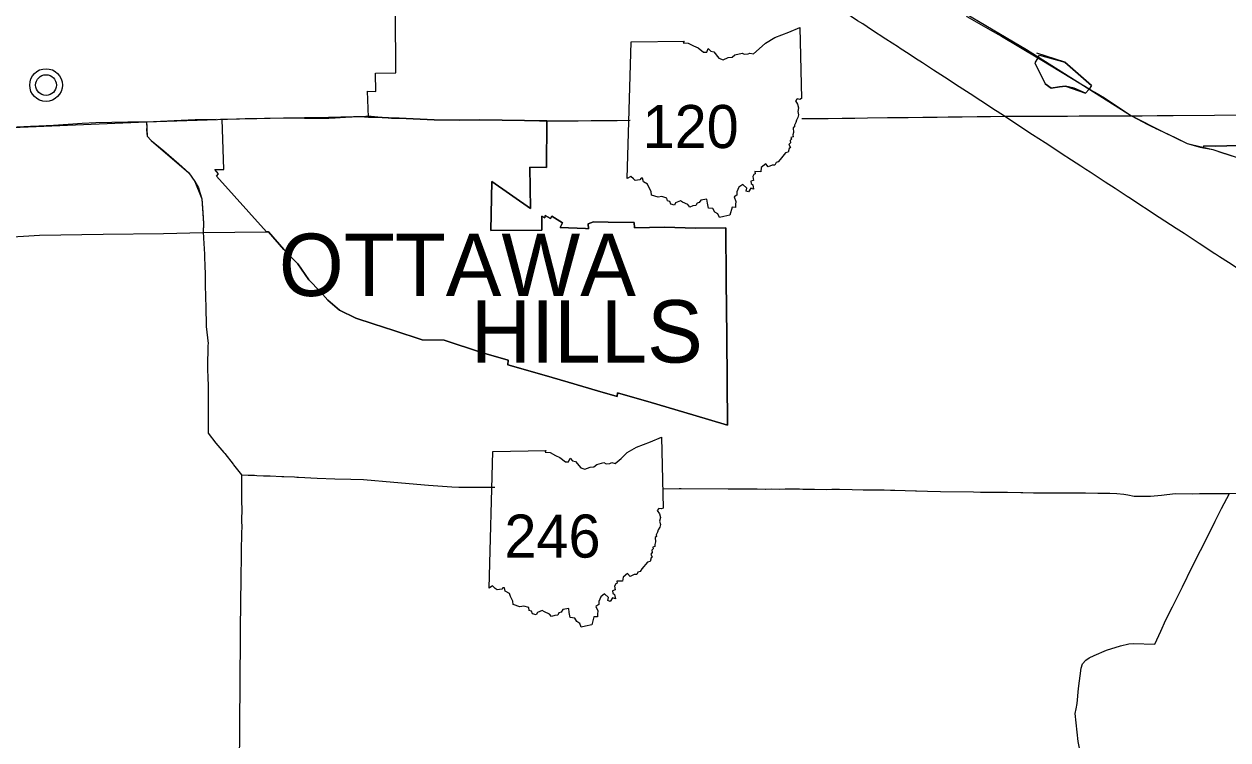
# Model space of a CAD drawing. Extents: x 0 to 750, y 0 to 507.
# Drawn here: x 255.1 to 327.4, y 253.1 to 296.1 of the extents above; entities that cross this region are included whole.
import ezdxf

# ---------------------------------------------------------------- set-up
doc = ezdxf.new("R2010")
doc.units = 0
for name, color, linetype in [('DV_X_Corp_Line', 7, 'Continuous'), ('GM_P_US_Alignment', 7, 'Continuous'), ('GM_X_Corporation_Text', 7, 'Continuous'), ('GM_X_Interchange_Ramps', 7, 'Continuous'), ('GM_X_Interstate_Route', 7, 'Continuous'), ('GM_X_State_Route', 7, 'Continuous'), ('GM_X_US_Route', 7, 'Continuous')]:
    doc.layers.add(name, color=color, linetype=linetype)

msp = doc.modelspace()

# ---------------------------------------------------------------- linework, layer by layer
at = {"layer": 'DV_X_Corp_Line'}
msp.add_lwpolyline([(253.725, 283.293), (255.984, 283.421), (259.807, 283.48), (263.433, 283.536), (265.817, 283.582), (269.608, 283.635), (269.738, 283.637), (270.649, 282.565), (271.501, 281.697), (272.156, 280.737), (272.844, 280.034), (273.309, 279.513), (273.998, 278.915), (274.979, 278.445), (276.03, 278.1), (277.271, 277.698), (278.976, 277.138), (280.281, 277.122), (282.541, 276.372), (284.129, 275.916), (284.12, 275.636), (286.297, 275.018), (287.744, 274.594), (289.497, 274.062), (290.692, 273.734), (290.711, 273.958), (292.724, 273.371), (295.222, 272.631), (297.303, 272.003), (297.281, 277.324), (297.242, 280.7), (297.204, 283.866), (295.385, 283.852), (293.52, 283.906), (291.717, 283.863), (291.71, 284.198), (290.143, 284.215), (289.26, 284.221), (288.948, 284.108), (288.961, 283.817), (288.776, 283.821), (287.254, 283.881), (287.408, 284.179), (286.756, 284.577), (286.685, 284.421), (286.349, 284.615), (286.348, 284.461), (286.159, 284.568), (286.159, 283.737), (283.104, 283.703), (283.161, 286.648), (285.472, 285.035), (285.447, 287.506), (286.445, 287.503), (286.46, 290.303), (282.424, 290.355), (281.185, 290.346), (279.697, 290.37), (278.437, 290.423), (277.587, 290.464), (277.422, 290.466), (277.167, 290.469), (276.955, 290.476), (276.566, 290.492), (275.749, 290.525), (275.693, 292.075), (276.179, 292.059), (276.163, 293.171), (277.395, 293.183), (277.361, 296.859)], dxfattribs=at)
msp.add_lwpolyline([(266.52, 287.376), (267.06, 287.376), (266.947, 290.404), (269.037, 290.446), (270.646, 290.48), (271.909, 290.47), (273.187, 290.459), (273.236, 290.458), (273.354, 290.464), (273.741, 290.484), (274.358, 290.515), (274.763, 290.535), (275.089, 290.551), (275.498, 290.535), (275.749, 290.525), (276.566, 290.492), (276.955, 290.476), (277.167, 290.469), (277.422, 290.466), (277.587, 290.464), (278.437, 290.423), (279.697, 290.37), (281.185, 290.346), (282.424, 290.355), (286.46, 290.303), (286.445, 287.503), (285.447, 287.506), (285.472, 285.035), (283.161, 286.648), (283.104, 283.703), (286.159, 283.737), (286.159, 284.568), (286.348, 284.461), (286.349, 284.615), (286.685, 284.421), (286.756, 284.577), (287.408, 284.179), (287.254, 283.881), (288.776, 283.821), (288.961, 283.817), (288.948, 284.108), (289.26, 284.221), (290.143, 284.215), (291.71, 284.198), (291.717, 283.863), (293.52, 283.906), (295.385, 283.852), (297.204, 283.866), (297.242, 280.7), (297.281, 277.324), (297.303, 272.003), (295.222, 272.631), (292.724, 273.371), (290.711, 273.958), (290.692, 273.734), (289.497, 274.062), (287.744, 274.594), (286.297, 275.018), (284.12, 275.636), (284.129, 275.916), (282.541, 276.372), (280.281, 277.122), (278.976, 277.138), (277.271, 277.698), (276.03, 278.1), (274.979, 278.445), (273.998, 278.915), (273.309, 279.513), (272.844, 280.034), (272.156, 280.737), (271.501, 281.697), (270.649, 282.565), (269.738, 283.637), (269.608, 283.635), (266.606, 286.972), (266.743, 287.112)], close=True, dxfattribs=at)
for radius in [0.982, 0.623]:
    msp.add_circle((256.371, 292.452), radius, dxfattribs=at)
at = {"layer": 'GM_P_US_Alignment'}
for points in [[(311.609, 296.75), (315.266, 294.587), (321.588, 290.607), (323.489, 289.631), (324.923, 288.947), (326.466, 288.573), (327.872, 288.11)], [(319.189, 292.421), (317.575, 293.818), (315.904, 294.369)], [(315.952, 294.081), (315.77, 293.779), (316.406, 292.52), (316.753, 292.272), (317.248, 292.351), (317.625, 292.381), (318.823, 291.965)], [(325.914, 288.681), (325.926, 288.807), (326.634, 288.783), (327.989, 288.815), (328.654, 288.98), (329.155, 289.177), (329.698, 289.612), (329.919, 289.883), (330.659, 291.217), (330.775, 291.18)], [(121.925, 287.941), (132.365, 287.845), (149.553, 287.753), (162.9, 288.301), (179.1, 288.291), (189.18, 288.131), (210.045, 288.307), (228.664, 288.186), (235.692, 288.005), (239.037, 288.663), (242.838, 289.339), (246.214, 288.691), (249.312, 288.691), (250.676, 289.038), (252.444, 289.82), (262.398, 290.25), (262.452, 289.379), (262.694, 289.121), (264.953, 287.17), (265.312, 286.649), (265.728, 285.606), (265.832, 284.123), (265.822, 283.582)], [(262.398, 290.25), (262.398, 290.25), (262.398, 290.25), (262.398, 290.25), (267.267, 290.408)]]:
    msp.add_lwpolyline(points, dxfattribs=at)
at = {"layer": 'GM_X_Interchange_Ramps'}
msp.add_lwpolyline([(330.723, 291.193), (330.659, 291.217), (330.478, 290.87), (330.379, 290.68), (330.372, 290.668), (330.084, 290.138), (329.919, 289.883), (329.698, 289.612), (329.426, 289.374), (329.155, 289.177), (328.654, 288.98), (327.989, 288.815), (326.634, 288.783), (326.584, 288.784), (325.926, 288.807), (325.914, 288.681)], dxfattribs=at)
at = {"layer": 'GM_X_Interstate_Route'}
for p, q in [((291.29, 286.835), (291.519, 295.043)), ((291.29, 286.835), (291.519, 295.043)), ((282.988, 262.218), (283.218, 270.425)), ((282.988, 262.218), (283.218, 270.425))]:
    msp.add_line(p, q, dxfattribs=at)
for points in [[(311.671, 296.587), (311.692, 296.575), (313.098, 295.775), (313.777, 295.389), (315.952, 294.081), (316.188, 293.94)], [(291.519, 295.043), (294.704, 295.096), (294.654, 294.997), (294.955, 294.976), (295.274, 294.801), (295.544, 294.69), (295.874, 294.429), (296.071, 294.432), (296.155, 294.646), (296.306, 294.481), (296.486, 294.451), (296.796, 294.058), (297.052, 293.973), (297.359, 294.108), (297.589, 294.13), (297.756, 294.263), (298.193, 294.377), (298.315, 294.309), (298.547, 294.323), (298.663, 294.373), (298.865, 294.328), (299.22, 294.626), (299.586, 294.978), (300.148, 295.31), (300.988, 295.625), (301.652, 295.906), (301.748, 291.647)], [(291.519, 295.043), (294.704, 295.096), (294.654, 294.997), (294.955, 294.976), (295.274, 294.801), (295.544, 294.69), (295.874, 294.429), (296.071, 294.432), (296.155, 294.646), (296.306, 294.481), (296.486, 294.451), (296.796, 294.058), (297.052, 293.973), (297.359, 294.108), (297.589, 294.13), (297.756, 294.263), (298.193, 294.377), (298.315, 294.309), (298.547, 294.323), (298.663, 294.373), (298.865, 294.328), (299.22, 294.626), (299.586, 294.978), (300.148, 295.31), (300.988, 295.625), (301.652, 295.906), (301.748, 291.647)], [(315.952, 294.081), (315.77, 293.779), (316.406, 292.52)], [(315.952, 294.081), (316.06, 294.244), (317.575, 293.818), (319.189, 292.421), (319.041, 292.203), (318.823, 291.965), (318.13, 292.272), (317.625, 292.381), (317.248, 292.351), (316.753, 292.272), (316.406, 292.52)], [(316.188, 293.94), (318.544, 292.524), (318.786, 292.379)], [(318.786, 292.379), (319.269, 292.088), (319.384, 292.019)], [(301.748, 291.647), (301.65, 291.587), (301.498, 291.615), (301.395, 291.496), (301.522, 291.297), (301.582, 291.086), (301.529, 290.854), (301.581, 290.662), (301.546, 290.502), (301.45, 290.343), (301.417, 290.191), (301.335, 290.031), (301.342, 289.941), (301.264, 289.87), (301.278, 289.604), (301.239, 289.456), (301.252, 289.329), (301.126, 289.295), (301.155, 289.19), (301.075, 289.109), (301.092, 288.969), (301.001, 288.88), (301.09, 288.701), (301.019, 288.644), (300.96, 288.427), (300.798, 288.383), (300.474, 287.986), (300.36, 287.835), (300.232, 287.798), (300.161, 287.644), (300.003, 287.643), (299.764, 287.536), (299.609, 287.72), (299.338, 287.499), (299.307, 287.243), (298.964, 287.251), (298.978, 287.121), (298.901, 287.084), (298.831, 286.954), (298.872, 286.724), (298.712, 286.665), (298.731, 286.531), (298.834, 286.45), (298.879, 286.194), (298.709, 286.246), (298.569, 286.03), (298.426, 286.081), (298.473, 286.263), (298.23, 286.483), (298.001, 286.307), (297.881, 286.026), (297.88, 285.837), (297.709, 285.723), (297.818, 285.456), (297.798, 285.272), (297.802, 285.098), (297.588, 285.104), (297.458, 284.633)], [(301.748, 291.647), (301.65, 291.587), (301.498, 291.615), (301.395, 291.496), (301.522, 291.297), (301.582, 291.086), (301.529, 290.854), (301.581, 290.662), (301.546, 290.502), (301.45, 290.343), (301.417, 290.191), (301.335, 290.031), (301.342, 289.941), (301.264, 289.87), (301.278, 289.604), (301.239, 289.456), (301.252, 289.329), (301.126, 289.295), (301.155, 289.19), (301.075, 289.109), (301.092, 288.969), (301.001, 288.88), (301.09, 288.701), (301.019, 288.644), (300.96, 288.427), (300.798, 288.383), (300.474, 287.986), (300.36, 287.835), (300.232, 287.798), (300.161, 287.644), (300.003, 287.643), (299.764, 287.536), (299.609, 287.72), (299.338, 287.499), (299.307, 287.243), (298.964, 287.251), (298.978, 287.121), (298.901, 287.084), (298.831, 286.954), (298.872, 286.724), (298.712, 286.665), (298.731, 286.531), (298.834, 286.45), (298.879, 286.194), (298.709, 286.246), (298.569, 286.03), (298.426, 286.081), (298.473, 286.263), (298.23, 286.483), (298.001, 286.307), (297.881, 286.026), (297.88, 285.837), (297.709, 285.723), (297.818, 285.456), (297.798, 285.272), (297.802, 285.098), (297.588, 285.104), (297.458, 284.633)], [(319.384, 292.019), (319.958, 291.674), (321.588, 290.607)], [(321.588, 290.607), (322.56, 290.074), (322.878, 289.923), (322.9, 289.912)], [(322.9, 289.912), (322.987, 289.871), (323.014, 289.858)], [(323.014, 289.858), (323.489, 289.631), (324.251, 289.271), (324.923, 288.947), (325.706, 288.722), (325.914, 288.681), (326.144, 288.636)], [(326.144, 288.636), (326.466, 288.573), (326.585, 288.532), (326.989, 288.396), (327.872, 288.11), (328.357, 288.012), (328.39, 288.006)], [(297.458, 284.633), (297.087, 284.543), (296.829, 284.489), (296.738, 284.703), (296.553, 284.816), (296.433, 285.031), (296.168, 285.061), (296.106, 285.356), (296.076, 285.597), (295.714, 285.537), (295.614, 285.391), (295.486, 285.351), (295.411, 285.203), (295.236, 285.191), (295.048, 285.121), (294.925, 285.266), (294.617, 285.412), (294.479, 285.487), (294.19, 285.37), (294.128, 285.232), (293.898, 285.293), (293.844, 285.447), (293.704, 285.493), (293.673, 285.657), (293.376, 285.744), (293.148, 285.709), (292.746, 285.841), (292.721, 286.056), (292.584, 286.318), (292.513, 286.5), (292.259, 286.639), (292.207, 286.855), (292.126, 286.849), (292.052, 286.761), (291.769, 286.721), (291.657, 286.809), (291.499, 286.96), (291.29, 286.835)], [(297.458, 284.633), (297.087, 284.543), (296.829, 284.489), (296.738, 284.703), (296.553, 284.816), (296.433, 285.031), (296.168, 285.061), (296.106, 285.356), (296.076, 285.597), (295.714, 285.537), (295.614, 285.391), (295.486, 285.351), (295.411, 285.203), (295.236, 285.191), (295.048, 285.121), (294.925, 285.266), (294.617, 285.412), (294.479, 285.487), (294.19, 285.37), (294.128, 285.232), (293.898, 285.293), (293.844, 285.447), (293.704, 285.493), (293.673, 285.657), (293.376, 285.744), (293.148, 285.709), (292.746, 285.841), (292.721, 286.056), (292.584, 286.318), (292.513, 286.5), (292.259, 286.639), (292.207, 286.855), (292.126, 286.849), (292.052, 286.761), (291.769, 286.721), (291.657, 286.809), (291.499, 286.96), (291.29, 286.835)], [(283.218, 270.425), (286.402, 270.478), (286.353, 270.379), (286.653, 270.358), (286.972, 270.183), (287.242, 270.072), (287.572, 269.811), (287.77, 269.814), (287.853, 270.028), (288.005, 269.863), (288.184, 269.834), (288.495, 269.441), (288.751, 269.356), (289.058, 269.49), (289.287, 269.512), (289.455, 269.646), (289.892, 269.759), (290.014, 269.691), (290.245, 269.705), (290.362, 269.755), (290.563, 269.71), (290.919, 270.009), (291.284, 270.361), (291.847, 270.693), (292.687, 271.007), (293.351, 271.288), (293.447, 267.029)], [(283.218, 270.425), (286.402, 270.478), (286.353, 270.379), (286.653, 270.358), (286.972, 270.183), (287.242, 270.072), (287.572, 269.811), (287.77, 269.814), (287.853, 270.028), (288.005, 269.863), (288.184, 269.834), (288.495, 269.441), (288.751, 269.356), (289.058, 269.49), (289.287, 269.512), (289.455, 269.646), (289.892, 269.759), (290.014, 269.691), (290.245, 269.705), (290.362, 269.755), (290.563, 269.71), (290.919, 270.009), (291.284, 270.361), (291.847, 270.693), (292.687, 271.007), (293.351, 271.288), (293.447, 267.029)], [(293.447, 267.029), (293.349, 266.97), (293.196, 266.998), (293.094, 266.878), (293.221, 266.679), (293.281, 266.468), (293.227, 266.236), (293.28, 266.045), (293.244, 265.885), (293.148, 265.725), (293.115, 265.573), (293.034, 265.413), (293.04, 265.323), (292.963, 265.252), (292.977, 264.986), (292.937, 264.838), (292.951, 264.711), (292.825, 264.678), (292.854, 264.572), (292.774, 264.491), (292.791, 264.351), (292.7, 264.262), (292.788, 264.083), (292.717, 264.027), (292.658, 263.809), (292.497, 263.765), (292.173, 263.368), (292.058, 263.218), (291.93, 263.18), (291.859, 263.026), (291.701, 263.025), (291.462, 262.918), (291.308, 263.102), (291.037, 262.881), (291.005, 262.625), (290.663, 262.633), (290.676, 262.504), (290.6, 262.466), (290.53, 262.336), (290.57, 262.106), (290.41, 262.047), (290.43, 261.914), (290.532, 261.832), (290.578, 261.576), (290.407, 261.628), (290.268, 261.413), (290.124, 261.463), (290.171, 261.646), (289.929, 261.865), (289.699, 261.689), (289.58, 261.409), (289.578, 261.22), (289.407, 261.105), (289.517, 260.839), (289.497, 260.655), (289.5, 260.48), (289.286, 260.486), (289.157, 260.015)], [(293.447, 267.029), (293.349, 266.97), (293.196, 266.998), (293.094, 266.878), (293.221, 266.679), (293.281, 266.468), (293.227, 266.236), (293.28, 266.045), (293.244, 265.885), (293.148, 265.725), (293.115, 265.573), (293.034, 265.413), (293.04, 265.323), (292.963, 265.252), (292.977, 264.986), (292.937, 264.838), (292.951, 264.711), (292.825, 264.678), (292.854, 264.572), (292.774, 264.491), (292.791, 264.351), (292.7, 264.262), (292.788, 264.083), (292.717, 264.027), (292.658, 263.809), (292.497, 263.765), (292.173, 263.368), (292.058, 263.218), (291.93, 263.18), (291.859, 263.026), (291.701, 263.025), (291.462, 262.918), (291.308, 263.102), (291.037, 262.881), (291.005, 262.625), (290.663, 262.633), (290.676, 262.504), (290.6, 262.466), (290.53, 262.336), (290.57, 262.106), (290.41, 262.047), (290.43, 261.914), (290.532, 261.832), (290.578, 261.576), (290.407, 261.628), (290.268, 261.413), (290.124, 261.463), (290.171, 261.646), (289.929, 261.865), (289.699, 261.689), (289.58, 261.409), (289.578, 261.22), (289.407, 261.105), (289.517, 260.839), (289.497, 260.655), (289.5, 260.48), (289.286, 260.486), (289.157, 260.015)], [(289.157, 260.015), (288.785, 259.925), (288.527, 259.871), (288.436, 260.085), (288.252, 260.198), (288.132, 260.414), (287.867, 260.443), (287.804, 260.739), (287.774, 260.979), (287.412, 260.92), (287.313, 260.773), (287.184, 260.733), (287.11, 260.585), (286.935, 260.573), (286.747, 260.503), (286.624, 260.648), (286.316, 260.794), (286.178, 260.869), (285.888, 260.753), (285.826, 260.614), (285.596, 260.675), (285.542, 260.829), (285.403, 260.876), (285.372, 261.039), (285.074, 261.126), (284.846, 261.092), (284.444, 261.223), (284.42, 261.438), (284.283, 261.7), (284.211, 261.882), (283.957, 262.021), (283.906, 262.238), (283.824, 262.231), (283.75, 262.143), (283.468, 262.103), (283.355, 262.192), (283.197, 262.342), (282.988, 262.218)], [(289.157, 260.015), (288.785, 259.925), (288.527, 259.871), (288.436, 260.085), (288.252, 260.198), (288.132, 260.414), (287.867, 260.443), (287.804, 260.739), (287.774, 260.979), (287.412, 260.92), (287.313, 260.773), (287.184, 260.733), (287.11, 260.585), (286.935, 260.573), (286.747, 260.503), (286.624, 260.648), (286.316, 260.794), (286.178, 260.869), (285.888, 260.753), (285.826, 260.614), (285.596, 260.675), (285.542, 260.829), (285.403, 260.876), (285.372, 261.039), (285.074, 261.126), (284.846, 261.092), (284.444, 261.223), (284.42, 261.438), (284.283, 261.7), (284.211, 261.882), (283.957, 262.021), (283.906, 262.238), (283.824, 262.231), (283.75, 262.143), (283.468, 262.103), (283.355, 262.192), (283.197, 262.342), (282.988, 262.218)]]:
    msp.add_lwpolyline(points, dxfattribs=at)
at = {"layer": 'GM_X_State_Route'}
for points in [[(313.503, 290.864), (313.421, 290.918), (312.522, 291.503), (311.89, 291.916), (311.227, 292.348), (310.351, 292.918), (309.696, 293.345), (309.033, 293.777), (308.614, 294.051), (308.219, 294.308), (307.682, 294.658), (307.577, 294.726), (306.822, 295.218), (305.96, 295.78), (305.436, 296.122), (305.129, 296.321), (304.734, 296.579), (304.319, 296.849), (304.11, 296.985), (303.753, 297.218)], [(313.951, 290.572), (313.503, 290.864)], [(262.398, 290.25), (265.323, 290.38), (266.587, 290.398)], [(266.848, 290.402), (267.267, 290.408), (268.333, 290.431), (270.643, 290.48), (270.656, 290.481), (271.897, 290.503), (273.337, 290.524), (275.581, 290.589)], [(275.581, 290.589), (275.712, 290.593), (277.13, 290.469), (277.241, 290.468), (277.419, 290.466), (277.585, 290.464), (279.604, 290.374), (279.694, 290.369), (281.195, 290.346), (282.419, 290.355)], [(282.419, 290.355), (285.244, 290.312), (286.008, 290.309), (286.14, 290.308)], [(286.14, 290.308), (286.403, 290.307), (287.504, 290.303), (288.333, 290.309), (289.126, 290.314), (289.974, 290.32), (290.679, 290.325), (291.459, 290.331)], [(301.769, 290.432), (302.4, 290.439), (303.351, 290.45), (304.202, 290.46), (304.953, 290.468), (305.724, 290.477), (306.925, 290.491), (307.313, 290.496), (307.99, 290.503), (308.17, 290.506), (309.055, 290.516), (309.904, 290.526), (310.575, 290.533), (311.406, 290.543), (312.304, 290.553), (313.116, 290.563), (313.951, 290.572)], [(313.951, 290.572), (314.656, 290.576), (315.639, 290.58), (316.35, 290.583), (316.716, 290.585), (317.739, 290.589), (318.441, 290.592), (319.711, 290.598)], [(321.422, 285.689), (321.315, 285.759), (320.603, 286.225), (320.008, 286.613), (319.097, 287.209), (318.835, 287.38), (318.542, 287.572), (317.969, 287.946), (317.367, 288.339), (316.8, 288.71), (316.39, 288.978), (315.645, 289.465), (314.693, 290.088), (313.951, 290.572)], [(319.711, 290.598), (319.985, 290.599), (320.416, 290.601), (321.588, 290.607), (322.234, 290.611), (323.117, 290.617)], [(323.117, 290.617), (323.244, 290.618), (324.019, 290.623)], [(324.019, 290.623), (324.047, 290.624), (324.085, 290.624), (326.573, 290.641), (328.797, 290.657)], [(323.25, 284.494), (321.422, 285.689)], [(326.584, 282.315), (325.646, 282.928), (324.739, 283.521), (324.259, 283.835), (323.255, 284.491), (323.25, 284.494)], [(328.843, 280.839), (328.482, 281.075), (327.409, 281.776), (326.868, 282.129), (326.622, 282.29), (326.584, 282.315)], [(268.122, 269.027), (268.518, 269.011), (268.703, 269.003), (268.892, 268.996), (269.037, 268.989), (269.442, 268.971), (269.62, 268.965), (269.698, 268.963), (269.829, 268.956), (270.53, 268.918), (270.653, 268.915), (271.307, 268.896), (271.43, 268.89), (271.537, 268.884)], [(271.537, 268.884), (271.544, 268.884), (272.662, 268.824), (273.725, 268.792), (274.689, 268.759)], [(274.689, 268.759), (275.451, 268.733), (277.27, 268.573), (279.34, 268.404), (280.195, 268.34), (280.75, 268.306), (281.179, 268.275), (282.1, 268.285), (283.332, 268.283)], [(293.438, 268.189), (294.399, 268.201)], [(294.399, 268.201), (294.53, 268.203), (297.35, 268.19)], [(297.35, 268.19), (297.829, 268.172), (297.884, 268.173)], [(297.884, 268.173), (298.536, 268.182), (299.091, 268.172), (299.593, 268.169), (299.623, 268.17)], [(299.623, 268.17), (299.933, 268.177), (300.424, 268.164), (300.775, 268.172), (301.126, 268.177), (301.633, 268.172), (301.843, 268.154), (302.529, 268.159), (303.244, 268.138), (303.583, 268.152), (304.042, 268.154), (304.794, 268.138), (305.467, 268.128), (306.174, 268.119)], [(306.174, 268.119), (306.727, 268.112), (307.11, 268.102), (307.37, 268.094)], [(307.37, 268.094), (308.608, 268.06), (308.671, 268.058)], [(308.671, 268.058), (309.33, 268.039), (310.105, 268.02), (312.096, 267.992), (312.512, 267.983), (313.373, 267.979), (314.143, 267.971), (314.934, 267.959), (315.045, 267.957)], [(315.045, 267.957), (315.696, 267.946), (316.552, 267.942), (317.024, 267.946), (317.313, 267.947), (318.088, 267.942), (318.828, 267.934), (319.555, 267.917), (320.282, 267.922)], [(320.282, 267.922), (320.708, 267.905), (321.116, 267.86), (321.363, 267.815), (321.75, 267.749), (322.175, 267.736), (322.726, 267.736), (323.381, 267.794), (324.209, 267.901), (325.259, 267.889), (325.676, 267.893), (325.733, 267.893)], [(325.733, 267.893), (326.4, 267.899)], [(326.4, 267.899), (327.468, 267.907), (327.886, 267.917), (329.087, 267.888), (330.053, 267.909), (330.248, 267.896), (331.211, 267.888), (332.928, 267.841), (333.076, 267.837), (334.574, 267.806), (336.601, 267.822), (337.909, 267.833), (339.332, 267.814), (340.841, 267.772), (341.233, 267.765), (342.853, 267.761)]]:
    msp.add_lwpolyline(points, dxfattribs=at)
at = {"layer": 'GM_X_US_Route'}
msp.add_line((252.444, 289.82), (255.439, 289.97), dxfattribs=at)
for points in [[(255.439, 289.97), (255.933, 289.995), (256.82, 290.049), (257.707, 290.103), (258.543, 290.154), (259.358, 290.203), (261.283, 290.233), (262.398, 290.25)], [(262.398, 290.25), (262.419, 289.946), (262.402, 289.756), (262.419, 289.555), (262.452, 289.379), (262.694, 289.121), (263.451, 288.495), (264.351, 287.723), (264.953, 287.17), (265.312, 286.649), (265.527, 286.266), (265.618, 285.984), (265.728, 285.606), (265.793, 284.793), (265.832, 284.123), (265.819, 283.643)], [(265.819, 283.643), (265.839, 283.239)], [(265.839, 283.239), (265.887, 282.288), (265.918, 281.411), (265.923, 281.268), (265.935, 280.559), (265.938, 280.423), (265.974, 279.069), (265.997, 278.043), (265.999, 277.938), (266.104, 276.919), (266.101, 276.787)], [(266.101, 276.787), (266.071, 275.493), (266.1, 274.731), (266.108, 274.503), (266.111, 273.779), (266.112, 273.614)], [(266.112, 273.614), (266.115, 273.047), (266.118, 272.251), (266.121, 271.524), (266.58, 270.933), (267.057, 270.369), (267.107, 270.309), (267.607, 269.664), (267.631, 269.633), (268.122, 269.027)], [(268.122, 269.027), (268.122, 267.955)], [(268.122, 267.955), (268.121, 267.614), (268.121, 267.485), (268.128, 266.898), (268.129, 266.763), (268.119, 266.507), (268.114, 266.394), (268.123, 266.136), (268.127, 266), (268.117, 265.445), (268.113, 265.275), (268.102, 264.669), (268.099, 264.534), (268.089, 263.958), (268.087, 263.818), (268.076, 263.176), (268.073, 263.016), (268.068, 262.326), (268.067, 262.194)], [(322.992, 258.836), (323.349, 259.622), (323.65, 260.303), (324.046, 261.098), (324.64, 262.289), (325.235, 263.484), (325.727, 264.471), (326.222, 265.465), (326.604, 266.232), (326.985, 266.995), (327.468, 267.907)], [(268.064, 261.845), (267.968, 251.349), (267.952, 250.641), (267.949, 250.523), (267.944, 250.115), (267.944, 250.113)], [(268.067, 262.194), (268.064, 261.93)], [(268.064, 261.93), (268.064, 261.845)], [(318.501, 250.086), (318.468, 250.462), (318.46, 251.007), (318.462, 251.452), (318.465, 252.226), (318.473, 252.492), (318.385, 253.001), (318.2, 254.677), (318.26, 254.96), (318.316, 255.285), (318.396, 256.181), (318.554, 257.401), (318.639, 257.658), (318.833, 257.885), (319.038, 258.024), (319.333, 258.164), (320.089, 258.485), (320.921, 258.739), (321.427, 258.872), (321.684, 258.875), (322.992, 258.836)]]:
    msp.add_lwpolyline(points, dxfattribs=at)

# ---------------------------------------------------------------- texts
at = {"layer": 'GM_X_Corporation_Text'}
for s, p in [('OTTAWA', (270.359, 279.771)), ('HILLS', (281.89, 275.771))]:
    msp.add_text(s, height=3.7501, rotation=0.00001, dxfattribs=at).set_placement(p)
at = {"layer": 'GM_X_Interstate_Route'}
for s, p in [('120', (292.213, 288.665)), ('246', (283.912, 264.048))]:
    msp.add_text(s, height=2.5875, dxfattribs=at).set_placement(p)

doc.saveas('drawing.dxf')
